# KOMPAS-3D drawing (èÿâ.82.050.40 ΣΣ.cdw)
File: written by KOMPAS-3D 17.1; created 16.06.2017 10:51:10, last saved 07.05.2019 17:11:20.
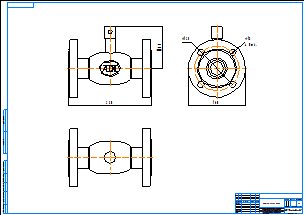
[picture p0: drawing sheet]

Sheet 1: A1, landscape

Title block, sheet 1: name: КШГ.82.050.40 фф; material: Внимание! Данный продукт является объектом авторского права ООО «Торговый Дом АДЛ». / Запрещается изменение, копирование, распространение / (в том числе путем копирования на другие сайты и ресурсы в Интернете) / или любое иное использование информации и объектов без предварительного / согласия правообладателя (ООО «Торговый Дом АДЛ»).; scale: 1:1; sheets: 1; organisation: ООО "Торговый дом АДЛ"; sheet format: A1; stored path: C:\Users\tra\Desktop\2д чертежи\Шаровые краны БИВАЛ\КШ_Бивал_серия_82_85\KOMPAS 2D\КШГ.82.050.40 фф.cdw

Views: Спереди 1, Проекционный вид 2, Проекционный вид 3
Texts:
  Klimkovich
  ADL
Dimensions and other numbers on the sheet: 230; 115,9; 160; 125; 18; 4 Отв.; 1:1; 1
